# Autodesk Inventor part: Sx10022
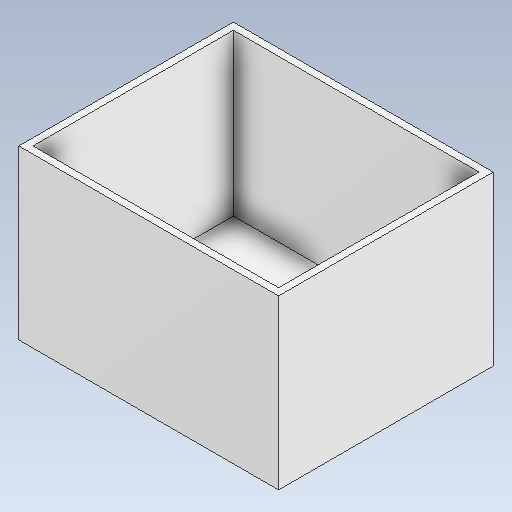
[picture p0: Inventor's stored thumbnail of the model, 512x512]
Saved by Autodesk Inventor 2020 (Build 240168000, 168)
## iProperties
Created: 2021-02
Part Number: Sx10022
Material: Generico
Document SubType Name: Modeling
Designer: zambolin
Density: 1 g/cm^3
Appearance: Default
Author: zambolin
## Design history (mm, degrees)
feature "Solido2"
node "Solido1"
